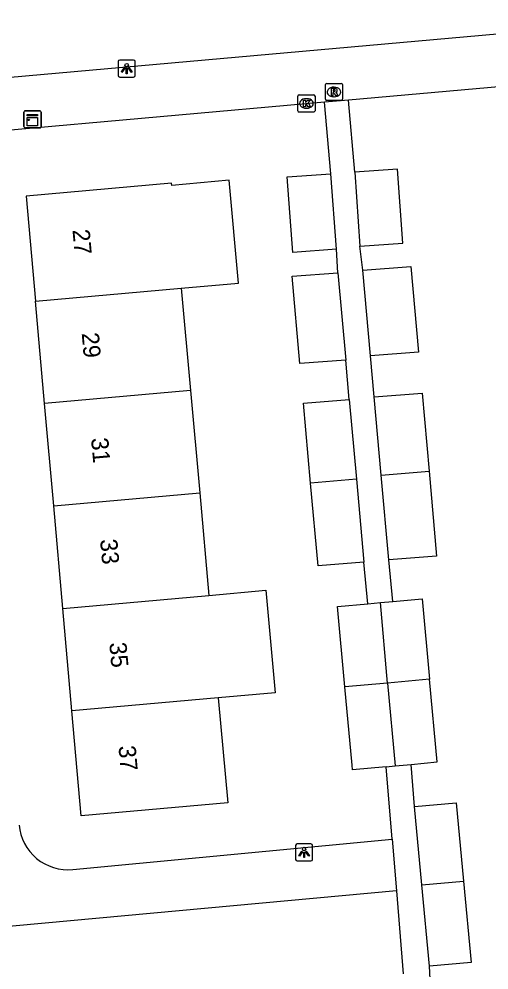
# Model space of a CAD drawing. Extents: x 160557 to 161245, y 385330 to 386505.
# Drawn here: x 160949.5 to 160976.9, y 385504.6 to 385560.1 of the extents above; entities that cross this region are included whole.
import ezdxf

# ---------------------------------------------------------------- set-up
doc = ezdxf.new("R2010")
doc.units = 0
for name, color, linetype in [('IMGEO_Kast', 7, 'Continuous'), ('IMGEO_Kolk', 7, 'Continuous'), ('IMGEO_Lichtpunt', 7, 'Continuous'), ('IMGEO_Pand', 7, 'Continuous'), ('IMGEO_Pand_nummerreeks', 7, 'Continuous'), ('IMGEO_Rioolput', 7, 'Continuous'), ('IMGEO_Voetpad_open', 7, 'Continuous')]:
    doc.layers.add(name, color=color, linetype=linetype)

msp = doc.modelspace()

# ---------------------------------------------------------------- linework, layer by layer
at = {"layer": 'IMGEO_Kast'}
for p, q in [((160949.771, 385553.852), (160949.771, 385554.693)), ((160949.771, 385554.693), (160949.771, 385553.852)), ((160949.846, 385554.777), (160950.687, 385554.777)), ((160950.687, 385554.777), (160949.846, 385554.777)), ((160950.771, 385554.702), (160950.771, 385553.861)), ((160950.771, 385553.861), (160950.771, 385554.702)), ((160950.696, 385553.777), (160949.855, 385553.777)), ((160949.855, 385553.777), (160950.696, 385553.777))]:
    msp.add_line(p, q, dxfattribs=at)
for points in [[(160949.966, 385554.567), (160950.566, 385554.567), (160950.566, 385554.482), (160949.966, 385554.482), (160949.966, 385554.567)], [(160949.966, 385554.392), (160950.566, 385554.392), (160950.566, 385553.903), (160949.966, 385553.903), (160949.966, 385554.392)]]:
    msp.add_lwpolyline(points, dxfattribs=at)
msp.add_circle((160950.05, 385554.241), 0.0377, dxfattribs=at)
for centre, start, end in [((160949.849, 385554.699), 92.4484, 184.2845), ((160949.849, 385554.699), 92.4484, 184.2845), ((160950.693, 385554.699), 2.4484, 94.2845), ((160950.693, 385554.699), 2.4484, 94.2845), ((160949.849, 385553.855), 182.4484, 274.2845), ((160949.849, 385553.855), 182.4484, 274.2845), ((160950.693, 385553.855), 272.4484, 4.2845), ((160950.693, 385553.855), 272.4484, 4.2845)]:
    msp.add_arc(centre, 0.0779, start, end, dxfattribs=at)
at = {"layer": 'IMGEO_Kolk'}
for p, q in [((160965.826, 385555.702), (160966.678, 385555.702)), ((160965.751, 385554.776), (160965.751, 385555.628)), ((160966.239, 385555.482), (160966.264, 385555.482)), ((160966.752, 385555.628), (160966.752, 385554.776)), ((160966.678, 385554.702), (160965.826, 385554.702)), ((160966.262, 385554.922), (160966.237, 385554.922))]:
    msp.add_line(p, q, dxfattribs=at)
for points in [[(160965.826, 385555.702), (160966.678, 385555.702)], [(160965.751, 385554.776), (160965.751, 385555.628)], [(160966.072, 385555.402), (160966.195, 385555.402), (160966.195, 385555.251), (160966.325, 385555.402), (160966.489, 385555.402), (160966.343, 385555.251), (160966.496, 385555.002), (160966.344, 385555.002), (160966.259, 385555.166), (160966.195, 385555.099), (160966.195, 385555.002), (160966.072, 385555.002), (160966.072, 385555.402)], [(160966.752, 385555.628), (160966.752, 385554.776)], [(160966.678, 385554.702), (160965.826, 385554.702)]]:
    msp.add_lwpolyline(points, dxfattribs=at)
for centre, start, end in [((160965.828, 385555.626), 91.552, 178.448), ((160965.828, 385555.626), 91.552, 178.448), ((160966.676, 385555.626), 1.552, 88.448), ((160966.676, 385555.626), 1.552, 88.448), ((160965.828, 385554.778), 181.552, 268.448), ((160965.828, 385554.778), 181.552, 268.448), ((160966.676, 385554.778), 271.552, 358.448), ((160966.676, 385554.778), 271.552, 358.448)]:
    msp.add_arc(centre, 0.0765, start, end, dxfattribs=at)
for centre, major_axis, ratio, start_param, end_param in [((160966.238, 385555.202), (-0.387, 0.002), 0.722429, 4.712389, 7.853982), ((160966.263, 385555.202), (-0.39, 0.002), 0.717154, 1.570796, 4.712389)]:
    msp.add_ellipse(centre, major_axis=major_axis, ratio=ratio, start_param=start_param, end_param=end_param, dxfattribs=at)
at = {"layer": 'IMGEO_Lichtpunt'}
for p, q in [((160955.265, 385557.643), (160955.265, 385556.836)), ((160955.265, 385557.643), (160955.265, 385556.836)), ((160956.167, 385557.738), (160955.359, 385557.738)), ((160956.167, 385557.738), (160955.359, 385557.738)), ((160956.261, 385556.836), (160956.261, 385557.643)), ((160956.261, 385556.836), (160956.261, 385557.643)), ((160955.359, 385556.742), (160956.167, 385556.742)), ((160955.359, 385556.742), (160956.167, 385556.742)), ((160965.615, 385511.896), (160965.615, 385511.089)), ((160965.615, 385511.896), (160965.615, 385511.089)), ((160966.517, 385511.991), (160965.709, 385511.991)), ((160966.517, 385511.991), (160965.709, 385511.991)), ((160966.611, 385511.089), (160966.611, 385511.896)), ((160966.611, 385511.089), (160966.611, 385511.896)), ((160965.709, 385510.995), (160966.517, 385510.995)), ((160965.709, 385510.995), (160966.517, 385510.995))]:
    msp.add_line(p, q, dxfattribs=at)
for points in [[(160955.639, 385557.307), (160955.678, 385557.279), (160955.49, 385557.017), (160955.452, 385557.044), (160955.639, 385557.307)], [(160955.741, 385557.259), (160955.788, 385557.259), (160955.788, 385556.937), (160955.741, 385556.937), (160955.741, 385557.259)], [(160955.851, 385557.279), (160955.889, 385557.306), (160956.076, 385557.044), (160956.037, 385557.016), (160955.851, 385557.279)], [(160965.989, 385511.56), (160966.028, 385511.532), (160965.84, 385511.27), (160965.802, 385511.297), (160965.989, 385511.56)], [(160966.091, 385511.512), (160966.138, 385511.512), (160966.138, 385511.19), (160966.091, 385511.19), (160966.091, 385511.512)], [(160966.201, 385511.532), (160966.239, 385511.559), (160966.426, 385511.297), (160966.387, 385511.269), (160966.201, 385511.532)]]:
    msp.add_lwpolyline(points, dxfattribs=at)
for centre in [(160955.764, 385557.441), (160966.114, 385511.694)]:
    msp.add_circle(centre, 0.0994, dxfattribs=at)
for centre, start, end in [((160955.359, 385557.643), 90, 180), ((160955.359, 385557.643), 90, 180), ((160956.167, 385557.643), 0, 90), ((160956.167, 385557.643), 0, 90), ((160955.359, 385556.836), 180, 270), ((160955.359, 385556.836), 180, 270), ((160956.167, 385556.836), 270, 0), ((160956.167, 385556.836), 270, 360), ((160965.709, 385511.896), 90, 180), ((160965.709, 385511.896), 90, 180), ((160966.517, 385511.896), 0, 90), ((160966.517, 385511.896), 0, 90), ((160965.709, 385511.089), 180, 270), ((160965.709, 385511.089), 180, 270), ((160966.517, 385511.089), 270, 0), ((160966.517, 385511.089), 270, 360)]:
    msp.add_arc(centre, 0.0946, start, end, dxfattribs=at)
at = {"layer": 'IMGEO_Pand'}
for points in [[(160969.366, 385546.867), (160971.872, 385547.041), (160971.571, 385551.368), (160969.065, 385551.194)], [(160958.939, 385544.422), (160962.291, 385544.721), (160961.746, 385550.718), (160958.394, 385550.42), (160958.383, 385550.545), (160949.896, 385549.79), (160950.441, 385543.664)], [(160968.006, 385546.698), (160965.458, 385546.504), (160965.121, 385550.92), (160967.67, 385551.097)], [(160968.006, 385546.698), (160967.67, 385551.097)], [(160969.065, 385551.194), (160969.366, 385546.867)], [(160968.543, 385540.222), (160965.872, 385540.019), (160965.415, 385545.119), (160968.087, 385545.322)], [(160968.087, 385545.322), (160968.543, 385540.222)], [(160969.547, 385545.475), (160972.334, 385545.688), (160972.781, 385540.695), (160969.994, 385540.482)], [(160969.994, 385540.482), (160969.547, 385545.475)], [(160950.441, 385543.664), (160958.939, 385544.422)], [(160958.939, 385544.422), (160959.481, 385538.447)], [(160950.973, 385537.688), (160950.441, 385543.664)], [(160959.481, 385538.447), (160950.973, 385537.688)], [(160959.481, 385538.447), (160960.023, 385532.472)], [(160970.209, 385538.085), (160972.996, 385538.298), (160973.403, 385533.746)], [(160970.62, 385533.502), (160970.209, 385538.085)], [(160951.506, 385531.712), (160950.973, 385537.688)], [(160966.496, 385533.047), (160966.078, 385537.713), (160968.75, 385537.917)], [(160968.75, 385537.917), (160969.165, 385533.285)], [(160970.62, 385533.502), (160973.403, 385533.746)], [(160971.061, 385528.577), (160970.62, 385533.502)], [(160973.403, 385533.746), (160973.847, 385528.789), (160971.061, 385528.577)], [(160969.165, 385533.285), (160966.496, 385533.047)], [(160969.599, 385528.431), (160966.928, 385528.227), (160966.496, 385533.047)], [(160969.165, 385533.285), (160969.599, 385528.431)], [(160951.506, 385531.712), (160960.023, 385532.472)], [(160960.023, 385532.472), (160960.566, 385526.495)], [(160952.038, 385525.735), (160951.506, 385531.712)], [(160952.038, 385525.735), (160960.566, 385526.495)], [(160960.566, 385526.495), (160963.886, 385526.791), (160964.418, 385520.815), (160961.108, 385520.52)], [(160971.288, 385526.143), (160972.998, 385526.303), (160973.435, 385521.598)], [(160952.57, 385519.759), (160952.038, 385525.735)], [(160968.493, 385521.158), (160968.057, 385525.842), (160969.825, 385526.007)], [(160969.825, 385526.007), (160970.563, 385526.076)], [(160970.563, 385526.076), (160971.288, 385526.143)], [(160970.989, 385521.38), (160970.563, 385526.076)], [(160970.989, 385521.38), (160968.493, 385521.158)], [(160973.435, 385521.598), (160970.989, 385521.38)], [(160970.989, 385521.38), (160971.428, 385516.545)], [(160972.356, 385516.631), (160973.884, 385516.773), (160973.435, 385521.598)], [(160970.898, 385516.496), (160968.944, 385516.313), (160968.919, 385516.582), (160968.493, 385521.158)], [(160961.108, 385520.52), (160961.664, 385514.396), (160953.115, 385513.635), (160952.57, 385519.759)], [(160961.108, 385520.52), (160952.57, 385519.759)], [(160970.898, 385516.496), (160971.428, 385516.545)], [(160971.428, 385516.545), (160972.356, 385516.631)], [(160972.561, 385514.167), (160974.996, 385514.393), (160975.42, 385509.823)], [(160972.984, 385509.61), (160972.561, 385514.167)], [(160972.984, 385509.61), (160975.42, 385509.823)], [(160975.42, 385509.823), (160975.86, 385505.075), (160973.425, 385504.85)], [(160973.425, 385504.85), (160972.984, 385509.61)]]:
    msp.add_lwpolyline(points, dxfattribs=at)
at = {"layer": 'IMGEO_Rioolput'}
for p, q in [((160967.357, 385555.447), (160967.357, 385556.299)), ((160967.432, 385556.373), (160968.284, 385556.373)), ((160968.358, 385556.299), (160968.358, 385555.447)), ((160967.845, 385556.153), (160967.87, 385556.153)), ((160968.284, 385555.373), (160967.432, 385555.373)), ((160967.868, 385555.593), (160967.843, 385555.593))]:
    msp.add_line(p, q, dxfattribs=at)
for points in [[(160967.357, 385555.447), (160967.357, 385556.299)], [(160967.432, 385556.373), (160968.284, 385556.373)], [(160968.358, 385556.299), (160968.358, 385555.447)], [(160967.946, 385556.071), (160967.694, 385556.073), (160967.694, 385555.673)], [(160967.694, 385555.673), (160967.818, 385555.673), (160967.818, 385555.835), (160967.829, 385555.835)], [(160967.872, 385555.992), (160967.818, 385555.992), (160967.818, 385555.911)], [(160967.818, 385555.911), (160967.87, 385555.911)], [(160967.876, 385555.806), (160967.947, 385555.673), (160968.087, 385555.673), (160968.022, 385555.799)], [(160968.284, 385555.373), (160967.432, 385555.373)]]:
    msp.add_lwpolyline(points, dxfattribs=at)
for centre, radius, start, end in [((160967.434, 385556.297), 0.0765, 91.552, 178.448), ((160967.434, 385556.297), 0.0765, 91.552, 178.448), ((160968.282, 385556.297), 0.0765, 1.552, 88.448), ((160968.282, 385556.297), 0.0765, 1.552, 88.448), ((160967.828, 385555.782), 0.0533, 26.0293, 88.6989), ((160967.854, 385556.1), 0.19, 274.7715, 282.9687), ((160967.878, 385555.896), 0.0964, 77.0061, 93.1865), ((160967.892, 385555.953), 0.0378, 276.6634, 79.6772), ((160967.945, 385555.961), 0.109, 350.3612, 89.416), ((160967.943, 385555.961), 0.112, 277.5842, 350.9817), ((160967.927, 385555.746), 0.108, 29.5134, 73.7905), ((160967.434, 385555.449), 0.0765, 181.552, 268.448), ((160967.434, 385555.449), 0.0765, 181.552, 268.448), ((160968.282, 385555.449), 0.0765, 271.552, 358.448), ((160968.282, 385555.449), 0.0765, 271.552, 358.448)]:
    msp.add_arc(centre, radius, start, end, dxfattribs=at)
for centre, major_axis, ratio, start_param, end_param in [((160967.844, 385555.873), (-0.387, 0.002), 0.722429, 4.712389, 7.853982), ((160967.869, 385555.873), (-0.39, 0.002), 0.717154, 1.570796, 4.712389)]:
    msp.add_ellipse(centre, major_axis=major_axis, ratio=ratio, start_param=start_param, end_param=end_param, dxfattribs=at)
at = {"layer": 'IMGEO_Voetpad_open'}
for points in [[(160931.719, 385555.2), (160986.979, 385560.13)], [(160987.774, 385557.095), (160968.699, 385555.397)], [(160967.302, 385555.272), (160948.115, 385553.564)], [(160968.699, 385555.397), (160967.302, 385555.272)], [(160967.67, 385551.097), (160967.302, 385555.272)], [(160969.065, 385551.194), (160968.699, 385555.397)], [(160969.547, 385545.475), (160969.366, 385546.867)], [(160968.087, 385545.322), (160968.006, 385546.698)], [(160968.75, 385537.917), (160968.543, 385540.222)], [(160970.209, 385538.085), (160969.994, 385540.482)], [(160971.288, 385526.143), (160971.061, 385528.577)], [(160969.825, 385526.007), (160969.599, 385528.431)], [(160971.25, 385512.259), (160970.898, 385516.496)], [(160972.561, 385514.167), (160972.356, 385516.631)], [(160952.62, 385510.494), (160971.25, 385512.259)], [(160971.25, 385512.259), (160971.5, 385509.25)], [(160971.5, 385509.25), (160925.409, 385505.018)], [(160971.5, 385509.25), (160971.897, 385504.418)], [(160973.568, 385502.193), (160973.425, 385504.85)]]:
    msp.add_lwpolyline(points, dxfattribs=at)
msp.add_arc((160952.348, 385513.36), 2.879, 185.2998, 275.4131, dxfattribs=at)

# ---------------------------------------------------------------- texts
at = {"layer": 'IMGEO_Pand_nummerreeks'}
for s, rotation, p in [('27', 275.0877, (160952.601, 385547.824)), ('29', 275.0878, (160953.137, 385541.798)), ('31', 275.0878, (160953.684, 385535.66)), ('33', 275.0878, (160954.21, 385529.747)), ('35', 275.0877, (160954.747, 385523.721)), ('37', 275.0878, (160955.283, 385517.695))]:
    msp.add_text(s, height=1, rotation=rotation, dxfattribs=at).set_placement(p)

doc.saveas('drawing.dxf')
